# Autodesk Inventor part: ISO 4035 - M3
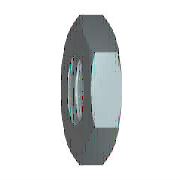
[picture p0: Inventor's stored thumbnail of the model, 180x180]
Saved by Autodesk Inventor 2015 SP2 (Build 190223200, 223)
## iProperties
IsCustomPart: 0
Created: 2012-02
Part Number: ISO 4035 - M3
Material: Edelstahl, 440C
Description: Sechskantmuttern, niedrige Form (mit Fase) - Produktklasse A und B
Document SubType Name: Modeling
Standard: ISO 4035
Designer: SteffenHaase
Standard Revision: Third edition 1999-08-15
Standards Organization: ISO
Language: de-DE
Size Designation: M3
Categories: <MemberInstance><Categories><Category DisplayName="Verbindungselemente" InternalName="e4da775c-781d-43d5-af7c-5136215cf5a6" Mnemonic="FSTN"><Category DisplayNam
Density: 7.75 g/cm^3
Mass: 0.269062 g
Surface Area: 0.792535 cm^2
Volume: 0.0347177 cm^3
Appearance: Halbpoliert
Author: SteffenHaase
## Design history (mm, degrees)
sketch "Skizze1"
  geometry: L1 (-3.175, 0)-(-1.588, 2.75); L2 (-1.588, 2.75)-(1.588, 2.75); L3 (1.588, 2.75)-(3.175, 0); L4 (3.175, 0)-(1.588, -2.75); L5 (1.588, -2.75)-(-1.588, -2.75); L6 (-1.588, -2.75)-(-3.175, 0); 2 further points
  constraints: 12 end point, 1 coincident, 1 horizontal, 11 other
  dimensions: "d0" = 6.35085 distance of L3.end L1.start (= 1.1547 x SW)
extrude "Körper" new body sketch "Skizze1" distance "d1" = 1.8 (= KOH); taper "d2" = 0 deg
sketch "Skizze2"
  geometry: L1 (0, 1.588)-(0, 3.175) reference; L2 (0, 3.175)-(1.8, 3.175) reference; L3 (1.8, 1.588)-(1.8, 3.175) reference; L4 (-0.36, 0)-(2.16, 0) reference; L5 (0.505, 3.175)-(0, 2.3); L6 (1.295, 3.175)-(1.8, 2.3)
  constraints: 4 end point, 4 point on line
  dimensions: "d3" = 30 deg angle of L1 L5 (= ANG1); "d4" = 30 deg angle of L3 L6 (= ANG2); "d5" = 4.6 diameter of L5.end L4 (= SW0); "d6" = 4.6 diameter of L6.end L4 (= SW01)
revolve "Fase1" sketch "Skizze2" stored, may be unused: angle "d7" = 90 deg
sketch "Skizze3"
  geometry: 4 further points
  constraints: 1 coincident, 1 other
hole "Gewinde" sketch "Skizze3" at (0, 0) diameter "d25" = 2.459; stored, may be unused: countersink angle "d29" = 82 deg, drill point angle "d31" = 118 deg; dims "d26" = 6, "d27" = 4, "d28" = 2, "d30" = 8
workaxis "Work Axis1"
workplane "Work Plane1"
body "Solid1"
chamfer "Fase2" distance "d8" = 0.27063 (= -0.5 x GD1 + 0.5 x NND); stored, may be unused: angle "d9" = 30 deg, second distance "d40" = 0.27063 (= -0.5 x GD1 + 0.5 x NND)
chamfer "Fase3" distance "d10" = 0.27063 (= -0.5 x GD1 + 0.5 x NND); stored, may be unused: angle "d11" = 30 deg, second distance "d41" = 0.27063 (= -0.5 x GD1 + 0.5 x NND)
other parameters: "ANG1" = 30 deg [user parameter; used in 1 equation term], "ANG2" = 30 deg [user parameter; used in 1 equation term], "NND" = 3 [user parameter; used in 4 equation terms], "KOH" = 1.8 [user parameter; used in 1 equation term], "SW" = 5.5 [user parameter; used in 2 equation terms], "SW0" = 4.6 [user parameter; used in 2 equation terms], "SW01" = 4.6 (= SW0) [user parameter; used in 1 equation term], "GD1" = 2.45873 (computed from THREADDIA, PTC, TOA) [user parameter; used in 4 equation terms], "d13" = 0, "d14" = 0, "d39" = 0, "d42" = 0, "GUL" = 0.27063 (= 0.541266 x PTC) [user parameter], "THREADDIA" = 3 [user parameter; used in 1 equation term], "TOA" = 30 deg [user parameter; used in 1 equation term], "PTC" = 0.5 [user parameter; used in 4 equation terms], "E0" = 6.3525 (= 1.155 x SW) [user parameter], "GAL" = 0.27063 (= 0.541266 x PTC) [user parameter]
